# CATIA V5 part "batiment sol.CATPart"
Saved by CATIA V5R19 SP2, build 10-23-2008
Part number: batiment sol
Bounding box of the stored display mesh (mm): x -59.769 to 141.608, y -91.45 to 149.362, z 0 to 0
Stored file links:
  Z:\42languedoc\batiment sol.CATPart
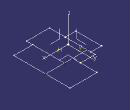
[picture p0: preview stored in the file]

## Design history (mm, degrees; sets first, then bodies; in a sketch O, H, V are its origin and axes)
AxisSystem1: origin (0, 0, 0), X (1, 0, 0), Y (0, 1, 0), Z (0, 0, 1)
Set1
  Sketch1 on XY plane of AxisSystem1, origin (0, 0, 0), H (1, 0, 0), V (0, 1, 0)
    line L1 (-19.3846, 69.0914) -> (-59.7693, 69.0914)
    line L2 (-59.7693, 69.0914) -> (-59.7693, -29.8724)
    line L3 (-59.7693, -29.8724) -> (-19.3846, -29.8724)
    line L4 (-19.3846, -29.8724) -> (-19.3846, 69.0914)
    point P5 (-19.3846, 85.5853)
    line L5 (-19.3846, 85.5853) -> (37.477, 85.5853)
    line L6 (37.477, 85.5853) -> (37.477, 54.7966)
    line L7 (37.477, 54.7966) -> (-19.3846, 54.7966)
    line L8 (-19.3846, 54.7966) -> (-19.3846, 85.5853)
    line L9 (-19.3846, 54.7966) -> (69.1385, 54.7966)
    line L10 (69.1385, 54.7966) -> (69.1385, -91.4498)
    line L11 (69.1385, -91.4498) -> (-19.3846, -91.4498)
    line L12 (-19.3846, -91.4498) -> (-19.3846, 54.7966)
    line L13 (37.477, 54.7966) -> (141.608, 54.7966)
    line L14 (141.608, 54.7966) -> (141.608, 149.362)
    line L15 (141.608, 149.362) -> (37.477, 149.362)
    line L16 (37.477, 149.362) -> (37.477, 54.7966)
    line L17 (141.608, 54.7966) -> (69.1385, 54.7966)
    line L18 (69.1385, 54.7966) -> (69.1385, -67.6252)
    line L19 (69.1385, -67.6252) -> (141.608, -67.6252)
    line L20 (141.608, -67.6252) -> (141.608, 54.7966)
    point P16 (69.1385, -67.6252)
    distance L1 L3 = 98.9638
    length L3 = 40.3847
    length L8 = 30.7887
    length L5 = 56.8616
    distance L18 L20 = 72.4695
    length L11 = 88.5232
    length L12 = 146.2464
    length L15 = 104.131 (reference)
    horizontal: L1 H, L3 H, L5 H, L7 H, L9 H, L11 H, L13 H, L15 H, L17 H, L19 H
    vertical: L2 V, L4 V, L6 V, L8 V, L10 V, L12 V, L14 V, L16 V, L18 V, L20 V
    coincidence: P5 L4, P16 L10
Body1 (main body)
